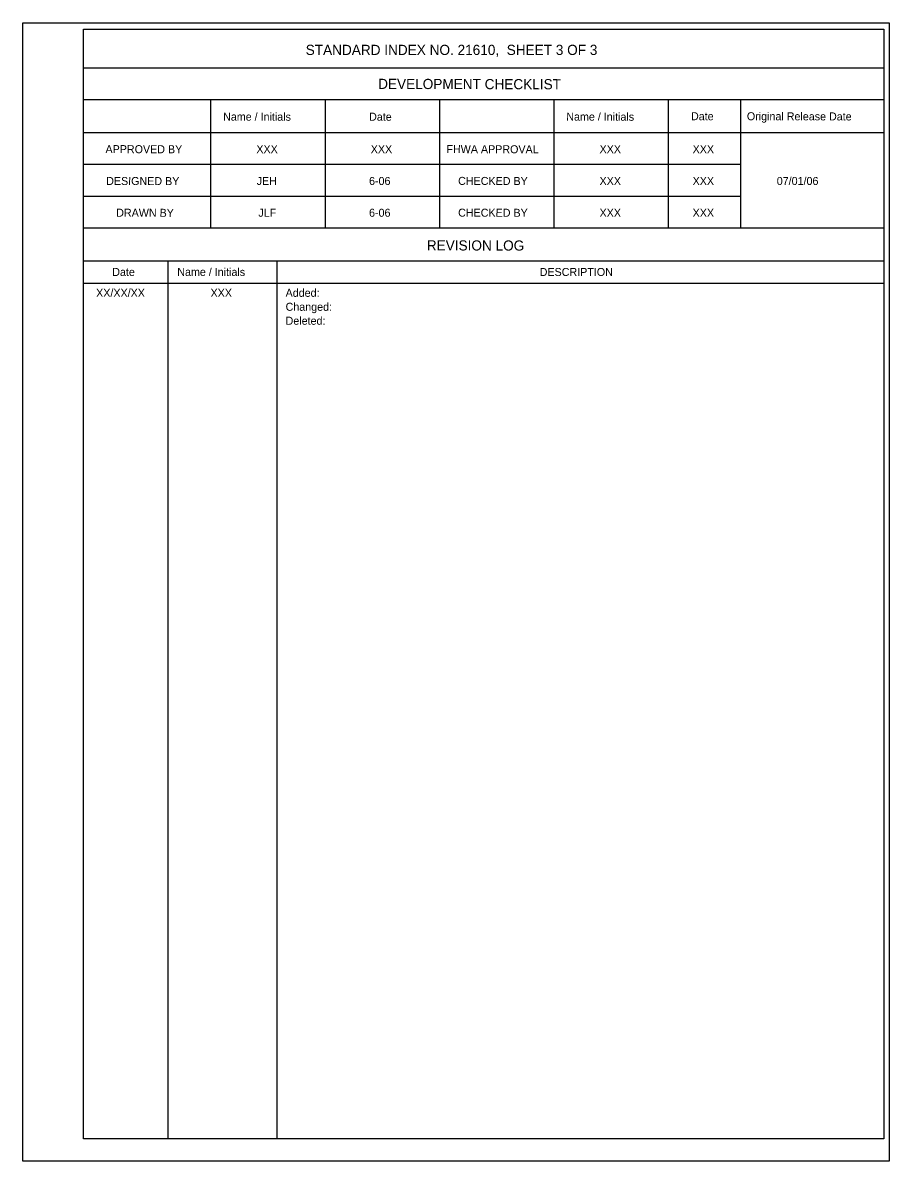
# Model space of a CAD drawing. Extents: x 10601.8 to 10619.6, y 76459.2 to 76469.
# Drawn here: x 10614.14 to 10619.6, y 76460.59 to 76467.76 of the extents above; entities that cross this region are included whole.
import ezdxf

# ---------------------------------------------------------------- set-up
doc = ezdxf.new("R2010")
doc.units = 0
for name, color, linetype in [('Border', 7, 'Continuous'), ('PlotBorder_dp', 7, 'Continuous'), ('TextStructures', 7, 'Continuous')]:
    doc.layers.add(name, color=color, linetype=linetype)

msp = doc.modelspace()

# ---------------------------------------------------------------- linework, layer by layer
at = {"layer": 'Border'}
for p, q in [((10619.5637, 76467.4758), (10614.5269, 76467.4758)), ((10619.5637, 76467.2758), (10614.5269, 76467.2758)), ((10615.3269, 76467.2758), (10615.3269, 76466.4688)), ((10616.0469, 76467.2758), (10616.0469, 76466.4688)), ((10616.7669, 76467.2758), (10616.7669, 76466.4688)), ((10617.4869, 76467.2758), (10617.4869, 76466.4688)), ((10618.2069, 76467.2758), (10618.2069, 76466.4688)), ((10618.6607, 76467.2758), (10618.6607, 76466.4688)), ((10619.5637, 76467.0688), (10614.5269, 76467.0688)), ((10618.6607, 76466.8688), (10614.5269, 76466.8688)), ((10618.6607, 76466.6688), (10614.5269, 76466.6688)), ((10619.5637, 76466.4688), (10614.5269, 76466.4688)), ((10619.5637, 76466.2619), (10614.5269, 76466.2619)), ((10615.057, 76466.2619), (10615.057, 76460.7353)), ((10615.7426, 76466.2619), (10615.7426, 76460.7353)), ((10619.5637, 76466.1209), (10614.5269, 76466.1209))]:
    msp.add_line(p, q, dxfattribs=at)
msp.add_lwpolyline([(10614.527, 76467.7209), (10619.5637, 76467.7209), (10619.5637, 76460.7353), (10614.527, 76460.7353)], close=True, dxfattribs=at)
at = {"layer": 'PlotBorder_dp'}
msp.add_line((10614.1443, 76460.5949), (10614.1443, 76460.5949), dxfattribs=at)
msp.add_lwpolyline([(10614.1443, 76467.7616), (10619.5977, 76467.7616), (10619.5977, 76460.5949), (10614.1443, 76460.5949)], close=True, dxfattribs=at)

# ---------------------------------------------------------------- texts
at = {"layer": 'TextStructures'}
for s, height, p in [('STANDARD INDEX NO. 21610,  SHEET 3 OF 3', 0.064, (10615.9251, 76467.5589)), ('XXX', 0.0504, (10615.6145, 76466.9405)), ('XXX', 0.0504, (10616.3345, 76466.9405)), ('XXX', 0.0504, (10617.7745, 76466.9405)), ('XXX', 0.0504, (10618.3603, 76466.9405)), ('JEH', 0.0504, (10615.6163, 76466.7405)), ('6-06', 0.0504, (10616.3237, 76466.7405)), ('XXX', 0.0504, (10617.7745, 76466.7405)), ('XXX', 0.0504, (10618.3603, 76466.7405)), ('07/01/06', 0.0504, (10618.8898, 76466.7405)), ('JLF', 0.0504, (10615.6269, 76466.5405)), ('6-06', 0.0504, (10616.3237, 76466.5405)), ('XXX', 0.0504, (10617.7745, 76466.5405)), ('XXX', 0.0504, (10618.3603, 76466.5405)), ('DESCRIPTION', 0.0504, (10617.3978, 76466.1676)), ('XX/XX/XX', 0.0504, (10614.6059, 76466.0364)), ('XXX', 0.0504, (10615.3261, 76466.0364)), ('Added:', 0.0504, (10615.7985, 76466.0364)), ('Changed:', 0.0504, (10615.7985, 76465.9485)), ('Deleted:', 0.0504, (10615.7985, 76465.8606))]:
    msp.add_text(s, height=height, dxfattribs=at).set_placement(p)
for s, height, p in [('DEVELOPMENT CHECKLIST', 0.064, (10616.3809, 76467.345)), ('Name / Initials', 0.0504, (10615.4051, 76467.1456)), ('Date', 0.0504, (10616.3238, 76467.1451)), ('Name / Initials', 0.0504, (10617.5651, 76467.1456)), ('Date', 0.0504, (10618.35, 76467.1481)), ('Original Release Date', 0.0504, (10618.7016, 76467.148)), ('APPROVED BY', 0.0504, (10614.6649, 76466.941)), ('FHWA APPROVAL', 0.0504, (10616.8107, 76466.941)), ('DESIGNED BY', 0.0504, (10614.6691, 76466.7406)), ('CHECKED BY', 0.0504, (10616.8844, 76466.741)), ('DRAWN BY', 0.0504, (10614.7323, 76466.5406)), ('CHECKED BY', 0.0504, (10616.8844, 76466.541)), ('REVISION LOG', 0.064, (10616.6872, 76466.3286)), ('Date', 0.0504, (10614.7075, 76466.1678)), ('Name / Initials', 0.0504, (10615.1167, 76466.1682))]:
    msp.add_text(s, height=height, rotation=359.87563, dxfattribs=at).set_placement(p)

doc.saveas('drawing.dxf')
